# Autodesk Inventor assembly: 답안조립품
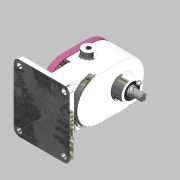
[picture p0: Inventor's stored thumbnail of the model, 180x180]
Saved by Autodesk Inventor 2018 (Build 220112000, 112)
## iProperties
Created: 2020-09
Part Number: 답안조립품
Material: 일반
Document SubType Name: Assembly
Designer: home
Author: home
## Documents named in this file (11)
- C:\Users\home\Desktop\700906V1034\답안조립품.iam
- C:\Users\home\Desktop\700906V1034\본체.ipt
- C:\Users\home\Desktop\700906V1034\커버.ipt
- C:\Users\home\Desktop\700906V1034\메인축.ipt
- C:\Users\home\Desktop\700906V1034\개스킷.ipt
- C:\Users\home\Desktop\700906V1034\볼트 M5.ipt
- C:\Users\home\Desktop\700906V1034\베어링부시.ipt
- C:\Users\home\Desktop\700906V1034\키 6 x 6 x 18.ipt
- C:\Users\home\Desktop\700906V1034\서브축.ipt
- C:\Users\home\Desktop\700906V1034\오일 실 16 28 7.ipt
- C:\Users\home\Desktop\700906V1034\스퍼기어.ipt
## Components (1 placed, 1 different names)
1. 개스킷:1
